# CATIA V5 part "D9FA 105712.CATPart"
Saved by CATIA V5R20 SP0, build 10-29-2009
Part number: D9FA 105712
Revision: ANY
Definition: UNKNOWN
Nomenclature: D9FA 105712
Source: Unknown
Bounding box of the stored display mesh (mm): x -5 to 5, y -10 to 10, z -5 to 5
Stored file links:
  C:\Users\Utente\Desktop\IO LAVORO\3D X SITO CF\CUMSA\3D files FA\FA 105712-21\D9FA 105712.CATPart
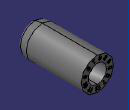
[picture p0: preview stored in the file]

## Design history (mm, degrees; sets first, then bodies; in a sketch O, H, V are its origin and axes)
Set1 "FacciaKO#NONE#6198"
  DatumSurface1 "Sup6198_1"
  DatumCurve1 "Crv6198_1"
Body1 "Cortar-Extruir5" (main body)
  Solid1: solid without history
